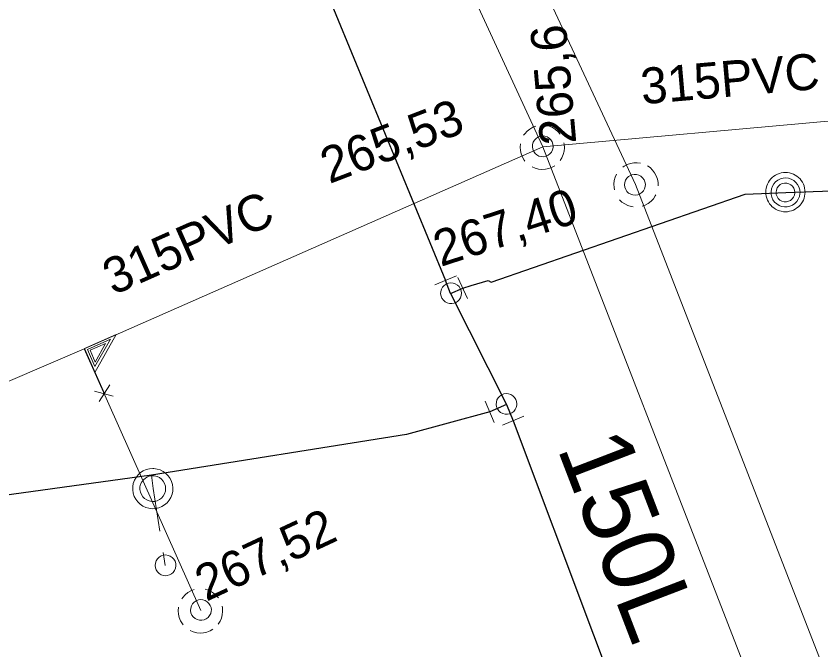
# Model space of a CAD drawing. Extents: x -732074 to -731966, y -1048695 to -1047982.
# Drawn here: x -732018.68 to -732000.79, y -1048554.48 to -1048540.38 of the extents above; entities that cross this region are included whole.
import ezdxf

# ---------------------------------------------------------------- set-up
doc = ezdxf.new("R2010")
doc.units = 0
doc.header["$LTSCALE"] = 0.32
doc.linetypes.add('MEDIUM_DASHED', pattern=[4.5, 3, -1.5])
doc.layers.add('1', color=7, linetype='Continuous')
for name, color, linetype, lineweight in [('18', 7, 'Continuous', 13), ('20', 7, 'Continuous', 13), ('49', 7, 'Continuous', 13), ('8', 7, 'Continuous', 13)]:
    doc.layers.add(name, color=color, linetype=linetype, lineweight=lineweight)

msp = doc.modelspace()

# ---------------------------------------------------------------- linework, layer by layer
at = {"layer": '18'}
for p, q in [((-732016.833, -1048548.956), (-732016.592, -1048548.583)), ((-732016.519, -1048548.831), (-732016.934, -1048548.72))]:
    msp.add_line(p, q, dxfattribs=at)
for points in [[(-732007.122, -1048542.827), (-732007.193, -1048542.855), (-732007.26, -1048542.894), (-732007.32, -1048542.942), (-732007.371, -1048542.999), (-732007.395, -1048543.033)], [(-732006.581, -1048543.01), (-732006.631, -1048542.952), (-732006.689, -1048542.902), (-732006.754, -1048542.861), (-732006.825, -1048542.832), (-732006.874, -1048542.818)], [(-732007.467, -1048543.219), (-732007.473, -1048543.296), (-732007.468, -1048543.373), (-732007.451, -1048543.448), (-732007.422, -1048543.519), (-732007.382, -1048543.585), (-732007.366, -1048543.607)], [(-732006.586, -1048543.596), (-732006.545, -1048543.531), (-732006.514, -1048543.461), (-732006.495, -1048543.386), (-732006.487, -1048543.31), (-732006.492, -1048543.233), (-732006.498, -1048543.198)], [(-732007.209, -1048543.736), (-732007.139, -1048543.767), (-732007.064, -1048543.786), (-732006.988, -1048543.793), (-732006.911, -1048543.788), (-732006.836, -1048543.771), (-732006.764, -1048543.743), (-732006.704, -1048543.708)], [(-732004.794, -1048543.653), (-732004.87, -1048543.643), (-732004.946, -1048543.645), (-732005.022, -1048543.659), (-732005.095, -1048543.684), (-732005.162, -1048543.721), (-732005.191, -1048543.741)], [(-732004.403, -1048544.158), (-732004.405, -1048544.082), (-732004.419, -1048544.006), (-732004.445, -1048543.934), (-732004.482, -1048543.866), (-732004.529, -1048543.806), (-732004.585, -1048543.752), (-732004.642, -1048543.713)], [(-732005.327, -1048543.896), (-732005.358, -1048543.966), (-732005.379, -1048544.039), (-732005.389, -1048544.116), (-732005.385, -1048544.192), (-732005.377, -1048544.243)], [(-732005.264, -1048544.464), (-732005.209, -1048544.516), (-732005.145, -1048544.56), (-732005.076, -1048544.594), (-732005.003, -1048544.617), (-732004.962, -1048544.624)], [(-732004.763, -1048544.611), (-732004.691, -1048544.584), (-732004.623, -1048544.547), (-732004.562, -1048544.499), (-732004.51, -1048544.443), (-732004.467, -1048544.379), (-732004.454, -1048544.355)], [(-732016.717, -1048548.777), (-732017.159, -1048547.775), (-732016.454, -1048547.465), (-732016.926, -1048548.304)], [(-732016.928, -1048548.175), (-732017.095, -1048547.795), (-732016.577, -1048547.567), (-732016.927, -1048548.177)], [(-732016.918, -1048548.08), (-732017.036, -1048547.813), (-732016.695, -1048547.663), (-732016.919, -1048548.081)], [(-732014.723, -1048553.137), (-732014.794, -1048553.165), (-732014.86, -1048553.204), (-732014.921, -1048553.252), (-732014.972, -1048553.309), (-732014.995, -1048553.343)], [(-732014.181, -1048553.32), (-732014.232, -1048553.262), (-732014.289, -1048553.212), (-732014.355, -1048553.171), (-732014.426, -1048553.142), (-732014.475, -1048553.128)], [(-732015.068, -1048553.529), (-732015.073, -1048553.606), (-732015.068, -1048553.683), (-732015.051, -1048553.758), (-732015.022, -1048553.829), (-732014.982, -1048553.895), (-732014.967, -1048553.917)], [(-732014.186, -1048553.906), (-732014.146, -1048553.841), (-732014.115, -1048553.771), (-732014.095, -1048553.696), (-732014.088, -1048553.62), (-732014.093, -1048553.543), (-732014.098, -1048553.508)], [(-732014.809, -1048554.046), (-732014.74, -1048554.077), (-732014.664, -1048554.096), (-732014.588, -1048554.103), (-732014.512, -1048554.098), (-732014.436, -1048554.081), (-732014.365, -1048554.053), (-732014.304, -1048554.018)]]:
    msp.add_lwpolyline(points, dxfattribs=at)
for points in [[(-732006.738, -1048543.279), (-732006.744, -1048543.227), (-732006.762, -1048543.177), (-732006.79, -1048543.133), (-732006.828, -1048543.096), (-732006.873, -1048543.069), (-732006.923, -1048543.053), (-732006.975, -1048543.048), (-732007.027, -1048543.055), (-732007.076, -1048543.074), (-732007.12, -1048543.104), (-732007.155, -1048543.143), (-732007.181, -1048543.188), (-732007.196, -1048543.239), (-732007.199, -1048543.291), (-732007.191, -1048543.343), (-732007.17, -1048543.391), (-732007.14, -1048543.434), (-732007.1, -1048543.469), (-732007.054, -1048543.493), (-732007.003, -1048543.507), (-732006.951, -1048543.509), (-732006.899, -1048543.499), (-732006.851, -1048543.477), (-732006.809, -1048543.445), (-732006.776, -1048543.405), (-732006.752, -1048543.358), (-732006.74, -1048543.307)], [(-732005.017, -1048543.925), (-732005.061, -1048543.952), (-732005.099, -1048543.989), (-732005.127, -1048544.033), (-732005.144, -1048544.083), (-732005.15, -1048544.136), (-732005.143, -1048544.188), (-732005.126, -1048544.237), (-732005.098, -1048544.281), (-732005.06, -1048544.318), (-732005.014, -1048544.345), (-732004.964, -1048544.36), (-732004.912, -1048544.365), (-732004.859, -1048544.357), (-732004.811, -1048544.337), (-732004.767, -1048544.308), (-732004.733, -1048544.269), (-732004.706, -1048544.223), (-732004.691, -1048544.172), (-732004.689, -1048544.121), (-732004.698, -1048544.068), (-732004.718, -1048544.02), (-732004.749, -1048543.978), (-732004.789, -1048543.943), (-732004.836, -1048543.919), (-732004.886, -1048543.906), (-732004.939, -1048543.904), (-732004.99, -1048543.915)], [(-732014.338, -1048553.589), (-732014.345, -1048553.537), (-732014.362, -1048553.487), (-732014.391, -1048553.443), (-732014.429, -1048553.406), (-732014.473, -1048553.379), (-732014.524, -1048553.363), (-732014.576, -1048553.358), (-732014.627, -1048553.365), (-732014.676, -1048553.384), (-732014.72, -1048553.414), (-732014.755, -1048553.453), (-732014.782, -1048553.498), (-732014.796, -1048553.549), (-732014.799, -1048553.601), (-732014.791, -1048553.653), (-732014.771, -1048553.701), (-732014.74, -1048553.744), (-732014.701, -1048553.779), (-732014.654, -1048553.803), (-732014.603, -1048553.817), (-732014.551, -1048553.819), (-732014.5, -1048553.809), (-732014.451, -1048553.787), (-732014.409, -1048553.755), (-732014.377, -1048553.715), (-732014.353, -1048553.668), (-732014.34, -1048553.617)]]:
    msp.add_lwpolyline(points, close=True, dxfattribs=at)
at = {"layer": '20'}
for p, q in [((-732004.91, -1048544.13), (-732020.46, -1048510.78)), ((-732004.91, -1048544.13), (-732020.46, -1048510.78)), ((-731997.949, -1048542.48), (-732006.969, -1048543.29)), ((-731997.949, -1048542.48), (-732006.969, -1048543.29)), ((-731996.42, -1048570.48), (-732006.969, -1048543.29)), ((-731996.42, -1048570.48), (-732006.969, -1048543.29)), ((-731994.199, -1048571.66), (-732004.91, -1048544.13)), ((-731994.199, -1048571.66), (-732004.91, -1048544.13))]:
    msp.add_line(p, q, dxfattribs=at)
for points in [[(-732006.969, -1048543.29), (-732012.87, -1048530.498), (-732018.316, -1048518.694), (-732022.17, -1048510.34)], [(-732006.969, -1048543.29), (-732012.87, -1048530.498), (-732018.316, -1048518.694), (-732022.17, -1048510.34)], [(-732019.71, -1048548.87), (-732017.166, -1048547.78), (-732006.969, -1048543.29)], [(-732019.71, -1048548.87), (-732017.166, -1048547.78), (-732006.969, -1048543.29)]]:
    msp.add_lwpolyline(points, dxfattribs=at)
at = {"layer": '49'}
msp.add_line((-732014.57, -1048553.6), (-732017.166, -1048547.78), dxfattribs=at)
msp.add_line((-732014.57, -1048553.6), (-732017.166, -1048547.78), dxfattribs=at)
at = {"layer": '8'}
for p, q in [((-732008.889, -1048546.161), (-732009.367, -1048546.358)), ((-732008.855, -1048546.192), (-732008.645, -1048546.665)), ((-732008.047, -1048549.418), (-732008.249, -1048548.942)), ((-732007.39, -1048549.277), (-732007.865, -1048549.482))]:
    msp.add_line(p, q, dxfattribs=at)
at = {"layer": '8', "lineweight": 25}
for p, q in [((-732009.02, -1048546.55), (-732009.129, -1048546.26)), ((-732009.02, -1048546.55), (-732008.75, -1048546.43)), ((-732009.02, -1048546.55), (-732007.776, -1048549.018)), ((-732007.776, -1048549.018), (-732008.149, -1048549.18)), ((-732007.776, -1048549.018), (-732007.629, -1048549.38))]:
    msp.add_line(p, q, dxfattribs=at)
at = {"layer": '8', "linetype": 'MEDIUM_DASHED'}
for p, q in [((-732015.672, -1048550.592), (-732015.631, -1048550.89)), ((-732015.631, -1048550.89), (-732015.368, -1048552.6))]:
    msp.add_line(p, q, dxfattribs=at)
at = {"layer": '8', "lineweight": 25}
for points in [[(-732043.199, -1048472.29), (-732042.854, -1048473.025), (-732034.093, -1048491.956), (-732023.079, -1048515.311), (-732013.932, -1048535.062), (-732012.27, -1048538.65), (-732009.129, -1048546.26)], [(-732001.568, -1048544.306), (-731995.059, -1048544.07), (-731994.09, -1048544.03)], [(-732008.75, -1048546.43), (-732008.559, -1048546.37), (-732008.18, -1048546.26), (-732008.12, -1048546.3), (-732002.469, -1048544.34), (-732001.568, -1048544.306)], [(-732008.149, -1048549.18), (-732009.997, -1048549.686), (-732015.672, -1048550.592), (-732026.249, -1048552.052)], [(-732007.629, -1048549.38), (-732002.27, -1048563.66), (-731996.51, -1048580.99), (-731995.102, -1048586.543), (-731992.07, -1048598.5), (-731991.625, -1048601.24), (-731990.239, -1048608.37)]]:
    msp.add_lwpolyline(points, dxfattribs=at)
at = {"layer": '8'}
msp.add_lwpolyline([(-732001.137, -1048544.295), (-732001.14, -1048544.25), (-732001.147, -1048544.205), (-732001.159, -1048544.16), (-732001.174, -1048544.118), (-732001.196, -1048544.077), (-732001.221, -1048544.038), (-732001.25, -1048544.003), (-732001.282, -1048543.97), (-732001.318, -1048543.942), (-732001.355, -1048543.917), (-732001.397, -1048543.896), (-732001.44, -1048543.879), (-732001.483, -1048543.867), (-732001.529, -1048543.86), (-732001.575, -1048543.858), (-732001.62, -1048543.86), (-732001.666, -1048543.867), (-732001.71, -1048543.879), (-732001.753, -1048543.896), (-732001.794, -1048543.917), (-732001.831, -1048543.942), (-732001.868, -1048543.97), (-732001.9, -1048544.003), (-732001.929, -1048544.038), (-732001.954, -1048544.077), (-732001.975, -1048544.118), (-732001.99, -1048544.16), (-732002.003, -1048544.205), (-732002.01, -1048544.25), (-732002.012, -1048544.296), (-732002.01, -1048544.341), (-732002.003, -1048544.386), (-732001.99, -1048544.431), (-732001.975, -1048544.473), (-732001.954, -1048544.514), (-732001.929, -1048544.553), (-732001.9, -1048544.588), (-732001.868, -1048544.621), (-732001.831, -1048544.649), (-732001.794, -1048544.674), (-732001.753, -1048544.695), (-732001.71, -1048544.712), (-732001.666, -1048544.723), (-732001.62, -1048544.731), (-732001.575, -1048544.733), (-732001.529, -1048544.731), (-732001.483, -1048544.723), (-732001.44, -1048544.712), (-732001.397, -1048544.695), (-732001.355, -1048544.674), (-732001.318, -1048544.649), (-732001.282, -1048544.621), (-732001.25, -1048544.588), (-732001.221, -1048544.553), (-732001.196, -1048544.514), (-732001.174, -1048544.473), (-732001.159, -1048544.431), (-732001.147, -1048544.386), (-732001.14, -1048544.341), (-732001.137, -1048544.296)], dxfattribs=at)
for points in [[(-732001.25, -1048544.303), (-732001.257, -1048544.242), (-732001.275, -1048544.182), (-732001.304, -1048544.127), (-732001.343, -1048544.079), (-732001.39, -1048544.039), (-732001.444, -1048544.009), (-732001.503, -1048543.989), (-732001.565, -1048543.982), (-732001.627, -1048543.986), (-732001.686, -1048544.002), (-732001.742, -1048544.03), (-732001.792, -1048544.067), (-732001.833, -1048544.114), (-732001.865, -1048544.167), (-732001.885, -1048544.226), (-732001.895, -1048544.287), (-732001.892, -1048544.349), (-732001.877, -1048544.409), (-732001.851, -1048544.466), (-732001.815, -1048544.516), (-732001.769, -1048544.559), (-732001.717, -1048544.591), (-732001.659, -1048544.614), (-732001.598, -1048544.624), (-732001.536, -1048544.623), (-732001.475, -1048544.61), (-732001.418, -1048544.585), (-732001.367, -1048544.55), (-732001.323, -1048544.506), (-732001.289, -1048544.454), (-732001.265, -1048544.397), (-732001.253, -1048544.336)], [(-732001.365, -1048544.303), (-732001.37, -1048544.254), (-732001.387, -1048544.207), (-732001.416, -1048544.166), (-732001.454, -1048544.133), (-732001.498, -1048544.109), (-732001.546, -1048544.097), (-732001.596, -1048544.096), (-732001.644, -1048544.108), (-732001.689, -1048544.13), (-732001.727, -1048544.163), (-732001.755, -1048544.203), (-732001.775, -1048544.25), (-732001.782, -1048544.299), (-732001.777, -1048544.349), (-732001.76, -1048544.396), (-732001.733, -1048544.438), (-732001.696, -1048544.472), (-732001.652, -1048544.496), (-732001.605, -1048544.51), (-732001.554, -1048544.511), (-732001.505, -1048544.501), (-732001.461, -1048544.479), (-732001.422, -1048544.447), (-732001.392, -1048544.408), (-732001.373, -1048544.362), (-732001.365, -1048544.312)], [(-732008.913, -1048546.755), (-732008.868, -1048546.727), (-732008.83, -1048546.69), (-732008.802, -1048546.646), (-732008.785, -1048546.596), (-732008.779, -1048546.544), (-732008.786, -1048546.492), (-732008.803, -1048546.442), (-732008.831, -1048546.398), (-732008.869, -1048546.362), (-732008.915, -1048546.334), (-732008.965, -1048546.319), (-732009.017, -1048546.314), (-732009.069, -1048546.322), (-732009.118, -1048546.342), (-732009.162, -1048546.371), (-732009.196, -1048546.41), (-732009.223, -1048546.455), (-732009.237, -1048546.506), (-732009.24, -1048546.558), (-732009.231, -1048546.61), (-732009.211, -1048546.658), (-732009.18, -1048546.701), (-732009.14, -1048546.736), (-732009.093, -1048546.76), (-732009.043, -1048546.773), (-732008.99, -1048546.775), (-732008.939, -1048546.765)], [(-732007.544, -1048549.007), (-732007.551, -1048548.955), (-732007.568, -1048548.905), (-732007.597, -1048548.861), (-732007.635, -1048548.824), (-732007.679, -1048548.797), (-732007.73, -1048548.781), (-732007.782, -1048548.776), (-732007.833, -1048548.783), (-732007.882, -1048548.802), (-732007.926, -1048548.832), (-732007.962, -1048548.871), (-732007.988, -1048548.916), (-732008.002, -1048548.967), (-732008.005, -1048549.019), (-732007.997, -1048549.071), (-732007.977, -1048549.119), (-732007.946, -1048549.162), (-732007.907, -1048549.197), (-732007.86, -1048549.221), (-732007.809, -1048549.235), (-732007.757, -1048549.237), (-732007.706, -1048549.227), (-732007.657, -1048549.205), (-732007.615, -1048549.173), (-732007.583, -1048549.133), (-732007.559, -1048549.086), (-732007.546, -1048549.035)], [(-732015.641, -1048550.442), (-732015.714, -1048550.448), (-732015.785, -1048550.466), (-732015.852, -1048550.495), (-732015.913, -1048550.535), (-732015.968, -1048550.584), (-732016.013, -1048550.641), (-732016.048, -1048550.705), (-732016.073, -1048550.774), (-732016.086, -1048550.846), (-732016.087, -1048550.92), (-732016.076, -1048550.992), (-732016.053, -1048551.062), (-732016.02, -1048551.126), (-732015.976, -1048551.185), (-732015.923, -1048551.236), (-732015.863, -1048551.277), (-732015.796, -1048551.308), (-732015.726, -1048551.328), (-732015.653, -1048551.336), (-732015.58, -1048551.333), (-732015.509, -1048551.317), (-732015.441, -1048551.29), (-732015.378, -1048551.252), (-732015.323, -1048551.204), (-732015.276, -1048551.148), (-732015.239, -1048551.085), (-732015.212, -1048551.017), (-732015.197, -1048550.945), (-732015.194, -1048550.872), (-732015.203, -1048550.799), (-732015.224, -1048550.729), (-732015.256, -1048550.663), (-732015.298, -1048550.603), (-732015.349, -1048550.551), (-732015.409, -1048550.508), (-732015.474, -1048550.475), (-732015.544, -1048550.454), (-732015.616, -1048550.444)], [(-732015.641, -1048550.603), (-732015.699, -1048550.609), (-732015.755, -1048550.627), (-732015.806, -1048550.655), (-732015.85, -1048550.694), (-732015.886, -1048550.74), (-732015.911, -1048550.793), (-732015.925, -1048550.85), (-732015.927, -1048550.909), (-732015.917, -1048550.966), (-732015.895, -1048551.021), (-732015.863, -1048551.07), (-732015.822, -1048551.111), (-732015.773, -1048551.143), (-732015.718, -1048551.165), (-732015.661, -1048551.175), (-732015.602, -1048551.174), (-732015.545, -1048551.16), (-732015.492, -1048551.135), (-732015.446, -1048551.099), (-732015.407, -1048551.055), (-732015.379, -1048551.004), (-732015.361, -1048550.948), (-732015.355, -1048550.89), (-732015.361, -1048550.832), (-732015.378, -1048550.776), (-732015.407, -1048550.725), (-732015.446, -1048550.681), (-732015.492, -1048550.646), (-732015.545, -1048550.621), (-732015.602, -1048550.607)], [(-732015.322, -1048552.825), (-732015.272, -1048552.811), (-732015.225, -1048552.786), (-732015.186, -1048552.752), (-732015.155, -1048552.709), (-732015.135, -1048552.66), (-732015.127, -1048552.608), (-732015.13, -1048552.556), (-732015.144, -1048552.506), (-732015.171, -1048552.46), (-732015.207, -1048552.421), (-732015.251, -1048552.392), (-732015.299, -1048552.374), (-732015.352, -1048552.366), (-732015.404, -1048552.371), (-732015.454, -1048552.387), (-732015.498, -1048552.415), (-732015.536, -1048552.451), (-732015.565, -1048552.496), (-732015.582, -1048552.545), (-732015.588, -1048552.598), (-732015.582, -1048552.65), (-732015.564, -1048552.699), (-732015.535, -1048552.744), (-732015.497, -1048552.78), (-732015.452, -1048552.807), (-732015.402, -1048552.823), (-732015.35, -1048552.828)]]:
    msp.add_lwpolyline(points, close=True, dxfattribs=at)

# ---------------------------------------------------------------- texts
at = {"layer": '1'}
for s, height, rotation, p in [('265,6 ', 0.8, 95, (-732006.223, -1048543.208)), ('315PVC', 0.8, 5, (-732004.76, -1048542.344)), ('265,53', 0.8, 21, (-732011.714, -1048544.118)), ('267,40', 0.8, 18, (-732009.24, -1048545.961)), ('315PVC', 0.8, 24, (-732016.518, -1048546.597)), ('150L', 1.6, 291, (-732006.658, -1048549.983)), ('267,52', 0.8, 25, (-732014.454, -1048553.41))]:
    msp.add_text(s, height=height, rotation=rotation, dxfattribs=at).set_placement(p)

doc.saveas('drawing.dxf')
